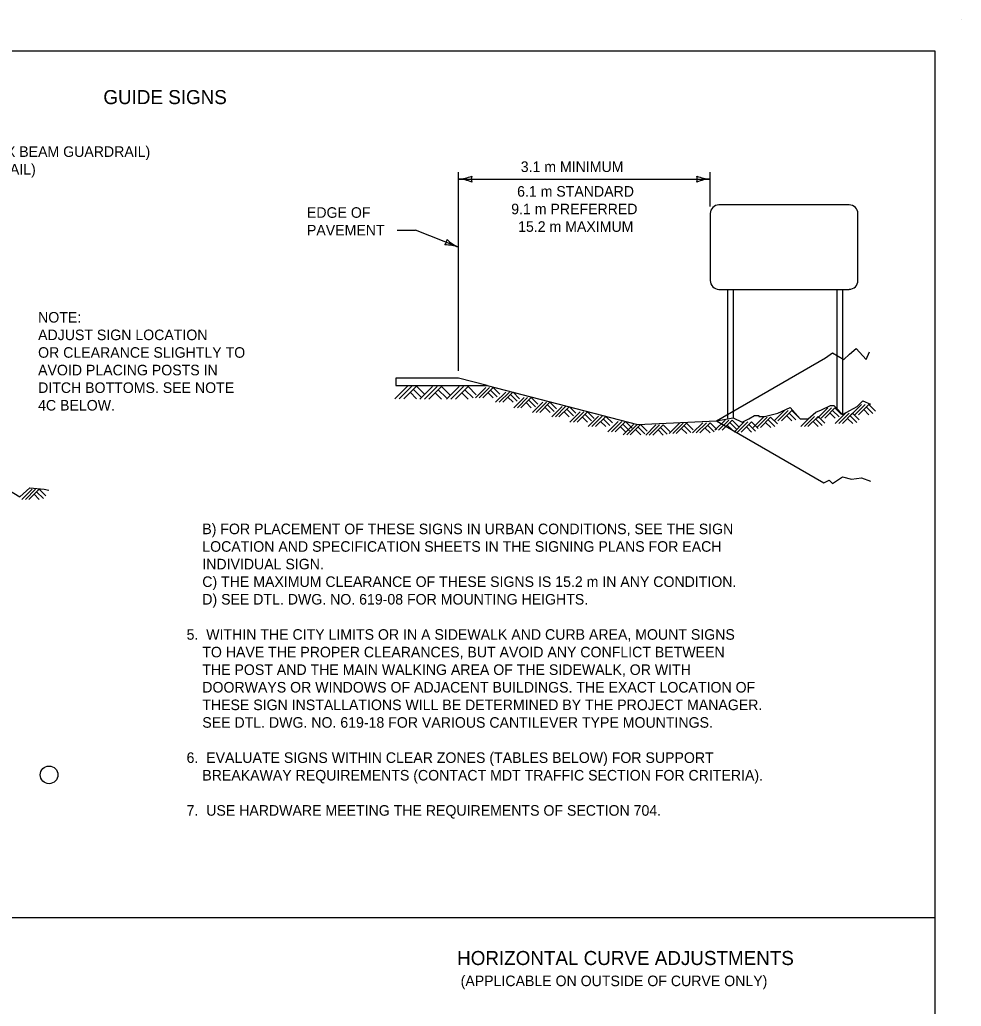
# Model space of a CAD drawing. Extents: x 49991.4 to 50021, y 49987.6 to 50011.4.
# Drawn here: x 50011.55 to 50016.9, y 49993.57 to 49999.18 of the extents above; entities that cross this region are included whole.
import ezdxf

# ---------------------------------------------------------------- set-up
doc = ezdxf.new("R2010")
doc.units = 0
for name, color, linetype in [('Level 1', 7, 'Continuous'), ('Level 2', 7, 'Continuous'), ('Level 3', 7, 'Continuous')]:
    doc.layers.add(name, color=color, linetype=linetype)

msp = doc.modelspace()

# ---------------------------------------------------------------- linework, layer by layer
at = {"layer": 'Level 1'}
for p, q in [((50016.9001, 49999.1756), (50016.9001, 49999.1756)), ((50016.263, 49998.1235), (50015.5229, 49998.1235)), ((50015.4729, 49998.0735), (50015.4729, 49997.6934)), ((50016.313, 49997.6934), (50016.313, 49998.0735)), ((50015.5229, 49997.6434), (50016.263, 49997.6434)), ((50015.5741, 49996.9115), (50015.5741, 49997.6434)), ((50015.6062, 49996.9147), (50015.6062, 49997.6434)), ((50016.1953, 49996.968), (50016.1953, 49997.6434)), ((50016.2274, 49996.9368), (50016.2274, 49997.6434)), ((50015.5091, 49996.8956), (50016.1291, 49997.2536)), ((50014.0419, 49997.1393), (50013.6857, 49997.1393)), ((50013.6857, 49997.1393), (50013.6857, 49997.0967)), ((50014.2056, 49997.0967), (50014.0419, 49997.1393)), ((50013.6806, 49997.022), (50013.7526, 49997.094)), ((50013.6857, 49997.0967), (50014.2058, 49997.0967)), ((50013.7059, 49997.022), (50013.7779, 49997.094)), ((50013.731, 49997.022), (50013.803, 49997.094)), ((50013.7853, 49997.0762), (50013.8321, 49997.0295)), ((50013.803, 49997.094), (50013.8499, 49997.0472)), ((50013.8231, 49997.019), (50013.8951, 49997.091)), ((50013.8484, 49997.019), (50013.9204, 49997.091)), ((50013.8735, 49997.019), (50013.9455, 49997.091)), ((50013.9455, 49997.091), (50013.9924, 49997.0442)), ((50013.9744, 49997.019), (50014.0464, 49997.091)), ((50013.9997, 49997.019), (50014.0717, 49997.091)), ((50014.0248, 49997.019), (50014.0968, 49997.091)), ((50014.0968, 49997.091), (50014.1437, 49997.0442)), ((50014.1395, 49997.0268), (50014.1978, 49997.0851)), ((50014.16, 49997.0268), (50014.2183, 49997.0851)), ((50014.1803, 49997.0268), (50014.2386, 49997.0851)), ((50014.2056, 49997.0967), (50014.2056, 49997.0967)), ((50014.2056, 49997.0967), (50015.0598, 49996.8746)), ((50014.2386, 49997.0851), (50014.2766, 49997.0472)), ((50013.7674, 49997.0583), (50013.8038, 49997.022)), ((50013.9099, 49997.0553), (50013.9463, 49997.019)), ((50013.9277, 49997.0732), (50013.9745, 49997.0265)), ((50014.0612, 49997.0553), (50014.0976, 49997.019)), ((50014.079, 49997.0732), (50014.1258, 49997.0265)), ((50014.2098, 49997.0563), (50014.2394, 49997.0268)), ((50014.2242, 49997.0708), (50014.2622, 49997.0329)), ((50014.2528, 49997.0015), (50014.3111, 49997.0598)), ((50014.2733, 49997.0015), (50014.3316, 49997.0598)), ((50014.2936, 49997.0015), (50014.3511, 49997.0589)), ((50014.3231, 49997.0309), (50014.3527, 49997.0015)), ((50014.3376, 49997.0455), (50014.3755, 49997.0076)), ((50014.3536, 49997.0582), (50014.3899, 49997.0219)), ((50014.3565, 49996.9699), (50014.4148, 49997.0282)), ((50014.377, 49996.9699), (50014.4353, 49997.0282)), ((50014.3973, 49996.9699), (50014.4556, 49997.0282)), ((50014.4556, 49997.0282), (50014.4936, 49996.9903)), ((50014.4268, 49996.9994), (50014.4563, 49996.9699)), ((50014.4413, 49997.0139), (50014.4792, 49996.976)), ((50014.4629, 49996.9437), (50014.5212, 49997.0021)), ((50014.4835, 49996.9437), (50014.5418, 49997.0021)), ((50014.5038, 49996.9437), (50014.5621, 49997.0021)), ((50014.5333, 49996.9731), (50014.5628, 49996.9437)), ((50014.5477, 49996.9877), (50014.5856, 49996.9498)), ((50014.5621, 49997.0021), (50014.6001, 49996.9641)), ((50014.5724, 49996.9186), (50014.6307, 49996.9769)), ((50014.5929, 49996.9186), (50014.6513, 49996.9769)), ((50014.6133, 49996.9186), (50014.6705, 49996.9758)), ((50014.6735, 49996.9751), (50014.7096, 49996.9391)), ((50016.0829, 49996.9118), (50016.1412, 49996.9701)), ((50016.1035, 49996.9118), (50016.1618, 49996.9701)), ((50016.1237, 49996.9118), (50016.1821, 49996.9701)), ((50016.1821, 49996.9701), (50016.2201, 49996.9322)), ((50016.2751, 49996.9309), (50016.3334, 49996.9892)), ((50016.2957, 49996.9309), (50016.354, 49996.9892)), ((50016.3159, 49996.9309), (50016.3743, 49996.9892)), ((50016.3599, 49996.9748), (50016.3978, 49996.937)), ((50016.3743, 49996.9892), (50016.4123, 49996.9513)), ((50014.6428, 49996.948), (50014.6722, 49996.9186)), ((50014.6572, 49996.9625), (50014.6951, 49996.9248)), ((50014.6759, 49996.8891), (50014.7342, 49996.9475)), ((50014.6965, 49996.8891), (50014.7548, 49996.9475)), ((50014.7167, 49996.8891), (50014.775, 49996.9475)), ((50014.7462, 49996.9186), (50014.7757, 49996.8891)), ((50014.7606, 49996.9331), (50014.7986, 49996.8952)), ((50014.775, 49996.9475), (50014.8131, 49996.9095)), ((50014.78, 49996.8635), (50014.8383, 49996.9218)), ((50014.8005, 49996.8635), (50014.8589, 49996.9218)), ((50014.8208, 49996.8635), (50014.879, 49996.9216)), ((50014.8795, 49996.9215), (50014.9172, 49996.8839)), ((50015.7175, 49996.8581), (50015.7758, 49996.9164)), ((50015.7381, 49996.8581), (50015.7964, 49996.9164)), ((50015.7583, 49996.8581), (50015.8167, 49996.9164)), ((50015.8167, 49996.9164), (50015.8547, 49996.8785)), ((50015.837, 49996.8963), (50015.8953, 49996.9546)), ((50015.8576, 49996.8963), (50015.9159, 49996.9546)), ((50015.8778, 49996.8963), (50015.9362, 49996.9546)), ((50015.9074, 49996.9257), (50015.9369, 49996.8963)), ((50015.9218, 49996.9402), (50015.9597, 49996.9024)), ((50015.9362, 49996.9546), (50015.9742, 49996.9167)), ((50015.9876, 49996.8633), (50016.0459, 49996.9216)), ((50016.0082, 49996.8633), (50016.0665, 49996.9216)), ((50016.0284, 49996.8633), (50016.0868, 49996.9216)), ((50016.0868, 49996.9216), (50016.1248, 49996.8837)), ((50016.1533, 49996.9412), (50016.1828, 49996.9118)), ((50016.1677, 49996.9557), (50016.2056, 49996.9179)), ((50016.1834, 49996.8807), (50016.2417, 49996.939)), ((50016.204, 49996.8807), (50016.2623, 49996.939)), ((50016.2242, 49996.8807), (50016.2826, 49996.939)), ((50016.2538, 49996.9101), (50016.2833, 49996.8807)), ((50016.2682, 49996.9246), (50016.3061, 49996.8868)), ((50016.2826, 49996.939), (50016.3206, 49996.9011)), ((50016.3455, 49996.9603), (50016.375, 49996.9309)), ((50014.8504, 49996.8929), (50014.8798, 49996.8635)), ((50014.8648, 49996.9074), (50014.9027, 49996.8696)), ((50014.8916, 49996.8339), (50014.9499, 49996.8922)), ((50014.9122, 49996.8339), (50014.9705, 49996.8922)), ((50014.9324, 49996.8339), (50014.9908, 49996.8922)), ((50014.962, 49996.8633), (50014.9915, 49996.8339)), ((50014.9764, 49996.8778), (50015.0143, 49996.84)), ((50014.9781, 49996.8167), (50015.0364, 49996.875)), ((50014.9908, 49996.8922), (50015.0288, 49996.8543)), ((50014.9987, 49996.8167), (50015.057, 49996.875)), ((50015.0189, 49996.8167), (50015.0773, 49996.875)), ((50015.0598, 49996.8746), (50015.5091, 49996.8956)), ((50015.0629, 49996.8606), (50015.1008, 49996.8228)), ((50015.0773, 49996.875), (50015.1153, 49996.8371)), ((50015.1063, 49996.8148), (50015.1646, 49996.8731)), ((50015.1269, 49996.8148), (50015.1852, 49996.8731)), ((50015.1471, 49996.8148), (50015.2055, 49996.8731)), ((50015.1911, 49996.8587), (50015.229, 49996.8209)), ((50015.2055, 49996.8731), (50015.2435, 49996.8352)), ((50015.2396, 49996.8236), (50015.2979, 49996.8819)), ((50015.2602, 49996.8236), (50015.3185, 49996.8819)), ((50015.2804, 49996.8236), (50015.3388, 49996.8819)), ((50015.31, 49996.853), (50015.3395, 49996.8236)), ((50015.3244, 49996.8675), (50015.3623, 49996.8297)), ((50015.3388, 49996.8819), (50015.3768, 49996.844)), ((50015.3729, 49996.827), (50015.4312, 49996.8853)), ((50015.3935, 49996.827), (50015.4518, 49996.8853)), ((50015.4137, 49996.827), (50015.4721, 49996.8853)), ((50015.4433, 49996.8564), (50015.4728, 49996.827)), ((50015.4577, 49996.8709), (50015.4956, 49996.8331)), ((50015.4721, 49996.8853), (50015.5101, 49996.8474)), ((50015.4993, 49996.8425), (50015.5576, 49996.9008)), ((50015.5091, 49996.8956), (50016.1195, 49996.5432)), ((50015.5199, 49996.8425), (50015.5782, 49996.9008)), ((50015.5401, 49996.8425), (50015.5985, 49996.9008)), ((50015.5697, 49996.8719), (50015.5992, 49996.8425)), ((50015.5841, 49996.8864), (50015.622, 49996.8486)), ((50015.5985, 49996.9008), (50015.6365, 49996.8629)), ((50015.6084, 49996.8322), (50015.6667, 49996.8905)), ((50015.629, 49996.8322), (50015.6873, 49996.8905)), ((50015.6492, 49996.8322), (50015.7076, 49996.8905)), ((50015.6788, 49996.8616), (50015.7083, 49996.8322)), ((50015.6932, 49996.8761), (50015.7311, 49996.8383)), ((50015.7076, 49996.8905), (50015.7456, 49996.8526)), ((50015.7879, 49996.8875), (50015.8174, 49996.8581)), ((50015.8023, 49996.902), (50015.8402, 49996.8642)), ((50016.058, 49996.8927), (50016.0875, 49996.8633)), ((50016.0724, 49996.9072), (50016.1103, 49996.8694)), ((50015.0485, 49996.8461), (50015.078, 49996.8167)), ((50015.1767, 49996.8442), (50015.2062, 49996.8148)), ((50011.5599, 49996.4495), (50011.6182, 49996.5079)), ((50011.5805, 49996.4495), (50011.6388, 49996.5079)), ((50011.6007, 49996.4495), (50011.659, 49996.5079)), ((50011.6302, 49996.479), (50011.6597, 49996.4495)), ((50011.6446, 49996.4935), (50011.6826, 49996.4556)), ((50011.659, 49996.5079), (50011.6971, 49996.4699))]:
    msp.add_line(p, q, dxfattribs=at)
msp.add_lwpolyline([(49999.3835, 49998.9992), (50016.7501, 49998.9992), (50016.7501, 49987.7988), (49999.3835, 49987.7988)], close=True, dxfattribs=at)
for points in [[(50016.1291, 49997.2536), (50016.1687, 49997.2819), (50016.2321, 49997.2438), (50016.2639, 49997.2755), (50016.3019, 49997.3072), (50016.359, 49997.2438), (50016.378, 49997.2882)], [(50015.5091, 49996.8956), (50015.6043, 49996.914), (50015.655, 49996.8886), (50015.6931, 49996.9076), (50015.7247, 49996.9267), (50015.7501, 49996.9267), (50015.7501, 49996.9204), (50015.7819, 49996.9204), (50015.8579, 49996.9394), (50015.9277, 49996.9711), (50015.9848, 49996.9076), (50016.0292, 49996.9076), (50016.0736, 49996.9457), (50016.1053, 49996.9584), (50016.156, 49996.9838), (50016.1751, 49996.9838), (50016.1878, 49996.9711), (50016.2258, 49996.933), (50016.3083, 49996.9774), (50016.3399, 49997.0092), (50016.3843, 49996.9901)], [(50016.1195, 49996.5432), (50016.1497, 49996.5588), (50016.1687, 49996.5398), (50016.2258, 49996.5779), (50016.2765, 49996.5652), (50016.3336, 49996.5715), (50016.3843, 49996.5524)], [(50011.1739, 49996.5018), (50011.2183, 49996.4891), (50011.2691, 49996.5144), (50011.3261, 49996.4954), (50011.4086, 49996.5081), (50011.4467, 49996.5271), (50011.5481, 49996.4637), (50011.6052, 49996.5144), (50011.6876, 49996.5081), (50011.7131, 49996.5017)]]:
    msp.add_lwpolyline(points, dxfattribs=at)
for centre, start, end in [((50015.5229, 49998.0735), 90, 180), ((50016.2629, 49998.0735), 0, 90), ((50015.5229, 49997.6934), 180, 270), ((50016.2629, 49997.6935), 270, 0)]:
    msp.add_arc(centre, 0.05, start, end, dxfattribs=at)
at = {"layer": 'Level 2'}
msp.add_circle((50011.7153, 49994.8842), 0.0501, dxfattribs=at)
at = {"layer": 'Level 3'}
for p, q in [((50014.0419, 49997.1793), (50014.0419, 49998.3101)), ((50015.4729, 49998.1135), (50015.4729, 49998.3101)), ((50014.0419, 49998.2701), (50015.4729, 49998.2701)), ((50013.6933, 49997.9799), (50013.7988, 49997.9799)), ((50014.0419, 49997.8836), (50013.7988, 49997.9799)), ((50008.0668, 49994.0732), (50016.7501, 49994.0732))]:
    msp.add_line(p, q, dxfattribs=at)
for centre, radius, start, end in [((50014.0304, 49998.5028), 0.233, 272.8273, 292.0772), ((50014.0327, 49998.048), 0.2223, 67.456, 87.6395), ((50014.1701, 49998.2701), 0.0548, 162.1388, 197.8612), ((50015.4821, 49998.4922), 0.2223, 247.456, 267.6395), ((50015.3447, 49998.2701), 0.0548, 342.1388, 17.8612), ((50015.4844, 49998.0374), 0.233, 92.8273, 112.0772), ((50013.9227, 49997.9308), 0.0548, 320.5287, 356.251), ((50014.1322, 49998.0867), 0.2223, 225.8458, 246.0294), ((50013.9669, 49997.663), 0.233, 71.2171, 90.467)]:
    msp.add_arc(centre, radius, start, end, dxfattribs=at)

# ---------------------------------------------------------------- texts
at = {"layer": 'Level 2'}
for s, height, p in [('GUIDE SIGNS', 0.08, (50012.0239, 49998.6959)), ('1.5 m STANDARD (W-BEAM OR BOX BEAM GUARDRAIL)', 0.06, (50010.1459, 49998.396)), ('3.1 m MINIMUM', 0.06, (50014.3962, 49998.3101)), ('3.1 m STANDARD (CABLE GUARDRAIL) ', 0.06, (50010.1459, 49998.296)), ('6.1 m STANDARD', 0.06, (50014.3755, 49998.1701)), ('EDGE OF', 0.06, (50013.1809, 49998.0499)), ('9.1 m PREFERRED', 0.06, (50014.3419, 49998.0701)), ('15.2 m MAXIMUM', 0.06, (50014.3812, 49997.9701)), ('PAVEMENT', 0.06, (50013.1809, 49997.9499)), ('NOTE:', 0.06, (50011.6528, 49997.4546)), ('ADJUST SIGN LOCATION', 0.06, (50011.6528, 49997.3546)), ('OR CLEARANCE SLIGHTLY TO', 0.06, (50011.6528, 49997.2546)), ('AVOID PLACING POSTS IN', 0.06, (50011.6528, 49997.1546)), ('DITCH BOTTOMS. SEE NOTE', 0.06, (50011.6528, 49997.0546)), ('4C BELOW.', 0.06, (50011.6528, 49996.9546)), ('    B) FOR PLACEMENT OF THESE SIGNS IN URBAN CONDITIONS, SEE THE SIGN', 0.06, (50012.4969, 49996.252)), ('    LOCATION AND SPECIFICATION SHEETS IN THE SIGNING PLANS FOR EACH', 0.06, (50012.4969, 49996.152)), ('    INDIVIDUAL SIGN.', 0.06, (50012.4969, 49996.052)), ('    C) THE MAXIMUM CLEARANCE OF THESE SIGNS IS 15.2 m IN ANY CONDITION.', 0.06, (50012.4969, 49995.952)), ('    D) SEE DTL. DWG. NO. 619-08 FOR MOUNTING HEIGHTS.', 0.06, (50012.4969, 49995.852)), ('5.  WITHIN THE CITY LIMITS OR IN A SIDEWALK AND CURB AREA, MOUNT SIGNS', 0.06, (50012.4969, 49995.652)), ('    TO HAVE THE PROPER CLEARANCES, BUT AVOID ANY CONFLICT BETWEEN', 0.06, (50012.4969, 49995.552)), ('    THE POST AND THE MAIN WALKING AREA OF THE SIDEWALK, OR WITH', 0.06, (50012.4969, 49995.452)), ('    DOORWAYS OR WINDOWS OF ADJACENT BUILDINGS. THE EXACT LOCATION OF', 0.06, (50012.4969, 49995.352)), ('    THESE SIGN INSTALLATIONS WILL BE DETERMINED BY THE PROJECT MANAGER.', 0.06, (50012.4969, 49995.252)), ('    SEE DTL. DWG. NO. 619-18 FOR VARIOUS CANTILEVER TYPE MOUNTINGS.', 0.06, (50012.4969, 49995.152)), ('6.  EVALUATE SIGNS WITHIN CLEAR ZONES (TABLES BELOW) FOR SUPPORT', 0.06, (50012.4969, 49994.952)), ('    BREAKAWAY REQUIREMENTS (CONTACT MDT TRAFFIC SECTION FOR CRITERIA).', 0.06, (50012.4969, 49994.852)), ('7.  USE HARDWARE MEETING THE REQUIREMENTS OF SECTION 704.', 0.06, (50012.4969, 49994.652)), ('HORIZONTAL CURVE ADJUSTMENTS', 0.08, (50014.0347, 49993.8033)), ('(APPLICABLE ON OUTSIDE OF CURVE ONLY)', 0.06, (50014.0546, 49993.6833))]:
    msp.add_text(s, height=height, dxfattribs=at).set_placement(p)

doc.saveas('drawing.dxf')
